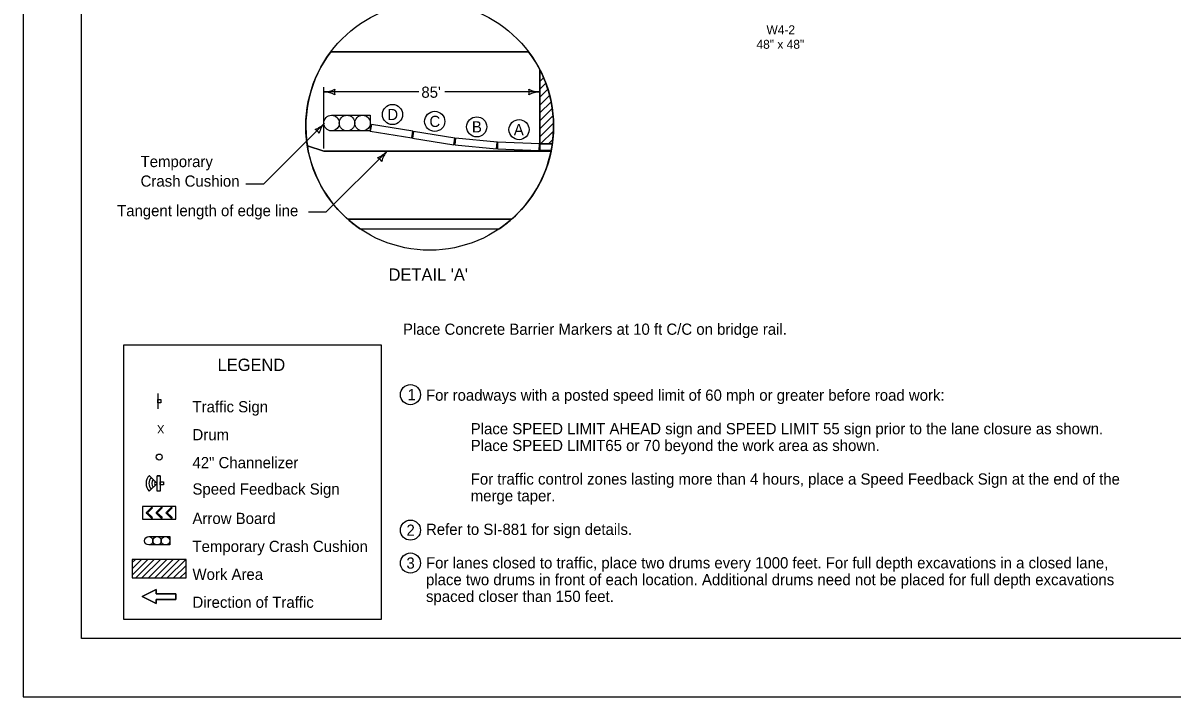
# Model space of a CAD drawing. Extents: x -2135039 to 114557, y -2139150 to -409929.
# Drawn here: x -2135039 to -2132982, y -2139150 to -2137945 of the extents above; entities that cross this region are included whole.
import ezdxf

# ---------------------------------------------------------------- set-up
doc = ezdxf.new("R2010")
doc.units = 0
for name, color, linetype in [('dsnDOTLogo', 7, 'Continuous'), ('dsnStdDimension', 7, 'Continuous'), ('dsnStdLabel', 7, 'Continuous'), ('dsnStdLineWork', 7, 'Continuous'), ('dsnStdNote', 7, 'Continuous'), ('dsnStdShading', 7, 'Continuous'), ('Level 1', 7, 'Continuous'), ('Level 2', 7, 'Continuous'), ('StdDetailLabel', 7, 'Continuous'), ('StdDimension', 7, 'Continuous'), ('StdNote', 7, 'Continuous')]:
    doc.layers.add(name, color=color, linetype=linetype)

msp = doc.modelspace()

# ---------------------------------------------------------------- linework, layer by layer
at = {"layer": 'dsnDOTLogo'}
msp.add_lwpolyline([(-2135038.9, -2139150.4), (-2131694.9, -2139150.4), (-2131694.9, -2136566.4), (-2135038.9, -2136566.4)], close=True, dxfattribs=at)
at = {"layer": 'dsnStdDimension'}
msp.add_line((-2134114.3, -2138156.3), (-2134114.3, -2138059.3), dxfattribs=at)
at = {"layer": 'dsnStdLabel'}
for p, q in [((-2134798, -2138607.5), (-2134798, -2138635)), ((-2134793.3, -2138754.5), (-2134793.3, -2138782)), ((-2134818.1, -2138820.1), (-2134809.3, -2138811.3)), ((-2134800.6, -2138820.1), (-2134791.8, -2138811.3)), ((-2134782.9, -2138820.1), (-2134774.1, -2138811.3)), ((-2134814.1, -2138863.4), (-2134776.6, -2138863.4)), ((-2134776.6, -2138863.4), (-2134776.6, -2138878.4)), ((-2134776.6, -2138878.4), (-2134814.1, -2138878.4)), ((-2134843.7, -2138909.9), (-2134838, -2138904.2)), ((-2134843.7, -2138921.2), (-2134826.7, -2138904.2)), ((-2134843.7, -2138932.5), (-2134815.4, -2138904.2)), ((-2134837.4, -2138937.5), (-2134804.1, -2138904.2)), ((-2134826.1, -2138937.5), (-2134792.8, -2138904.2)), ((-2134814.7, -2138937.5), (-2134781.5, -2138904.2)), ((-2134803.4, -2138937.5), (-2134770.1, -2138904.2)), ((-2134792.1, -2138937.5), (-2134758.8, -2138904.2)), ((-2134780.8, -2138937.5), (-2134747.5, -2138904.2)), ((-2134769.5, -2138937.5), (-2134747, -2138915)), ((-2134758.2, -2138937.5), (-2134747, -2138926.4))]:
    msp.add_line(p, q, dxfattribs=at)
for points in [[(-2134797.9, -2138623.9), (-2134797.9, -2138618.3), (-2134792.3, -2138618.3), (-2134792.3, -2138623.9)], [(-2134798.9, -2138782), (-2134798.9, -2138754.5), (-2134793.3, -2138754.5), (-2134793.3, -2138782)], [(-2134793.3, -2138771), (-2134793.3, -2138765.3), (-2134787.6, -2138765.3), (-2134787.6, -2138771)], [(-2134765.3, -2138809.4), (-2134825.3, -2138809.4), (-2134825.3, -2138832.3), (-2134765.3, -2138832.3)], [(-2134843.7, -2138904.2), (-2134843.7, -2138937.5), (-2134747, -2138937.5), (-2134747, -2138904.2)], [(-2134765.7, -2138965.9), (-2134765.7, -2138975.9), (-2134800.7, -2138975.9), (-2134800.7, -2138983.4), (-2134825.7, -2138970.9), (-2134800.7, -2138958.4), (-2134800.7, -2138965.9)]]:
    msp.add_lwpolyline(points, close=True, dxfattribs=at)
for points in [[(-2134809.3, -2138830.4), (-2134809.3, -2138830.4), (-2134818.1, -2138821.6), (-2134818.1, -2138821.6)], [(-2134807.9, -2138812.8), (-2134807.9, -2138812.8), (-2134816.4, -2138820.9), (-2134807.9, -2138828.9)], [(-2134791.8, -2138830.4), (-2134791.8, -2138830.4), (-2134800.6, -2138821.6), (-2134800.6, -2138821.6)], [(-2134790.3, -2138812.8), (-2134790.4, -2138812.8), (-2134798.8, -2138820.9), (-2134790.3, -2138828.9)], [(-2134774.1, -2138830.4), (-2134774.1, -2138830.4), (-2134782.9, -2138821.6), (-2134783, -2138821.6)], [(-2134772.7, -2138812.8), (-2134772.7, -2138812.8), (-2134781.2, -2138820.9), (-2134772.7, -2138828.9)], [(-2134800.7, -2138965.9), (-2134800.7, -2138958.4), (-2134825.7, -2138970.9), (-2134800.7, -2138983.4), (-2134800.7, -2138975.9), (-2134765.7, -2138975.9), (-2134765.7, -2138965.9), (-2134800.7, -2138965.9)]]:
    msp.add_lwpolyline(points, dxfattribs=at)
for centre, radius in [((-2134311.5, -2138129.5), 221.6), ((-2134487.1, -2138123.6), 13.9), ((-2134459.4, -2138123.6), 13.9), ((-2134431.6, -2138123.6), 13.9), ((-2134795.3, -2138721.1), 5.37), ((-2134795.3, -2138721.1), 5.37), ((-2134814.1, -2138870.9), 7.5), ((-2134814.1, -2138870.9), 7.5), ((-2134799.1, -2138870.9), 7.5), ((-2134799.1, -2138870.9), 7.5), ((-2134784.1, -2138870.9), 7.5), ((-2134784.1, -2138870.9), 7.5)]:
    msp.add_circle(centre, radius, dxfattribs=at)
for centre, start, end in [((-2134817.4, -2138820.9), 134.1616, 224.6098), ((-2134808.6, -2138812), 315.0975, 135.281), ((-2134799.9, -2138820.9), 134.1616, 224.6098), ((-2134791, -2138812), 315.0975, 135.281), ((-2134782.2, -2138820.9), 134.1616, 224.6098), ((-2134773.4, -2138812), 315.0975, 135.281), ((-2134808.6, -2138829.7), 226.201, 47.3602), ((-2134791, -2138829.7), 226.201, 47.3602), ((-2134773.4, -2138829.7), 226.201, 47.3602)]:
    msp.add_arc(centre, 1.03, start, end, dxfattribs=at)
at = {"layer": 'dsnStdLineWork'}
for p, q in [((-2134488.4, -2137996.1), (-2134134.6, -2137996.1)), ((-2134114.3, -2138160.9), (-2134114.3, -2138028.4)), ((-2134114.3, -2138034.9), (-2134112.2, -2138032.7)), ((-2134114.3, -2138049), (-2134107.7, -2138042.4)), ((-2134114.3, -2138063.1), (-2134103.7, -2138052.5)), ((-2134114.3, -2138077.3), (-2134100.1, -2138063.1)), ((-2134114.3, -2138091.4), (-2134097, -2138074.1)), ((-2134114.3, -2138105.6), (-2134094.3, -2138085.6)), ((-2134114.3, -2138119.7), (-2134092.2, -2138097.6)), ((-2134114.3, -2138133.9), (-2134090.8, -2138110.3)), ((-2134114.3, -2138148), (-2134090, -2138123.7)), ((-2134113.1, -2138160.9), (-2134090.1, -2138137.9)), ((-2134530.3, -2138164.4), (-2134501, -2138173.9)), ((-2134098.9, -2138160.9), (-2134091.2, -2138153.1)), ((-2134501, -2138173.9), (-2134094.4, -2138173.9)), ((-2134458.1, -2138295.7), (-2134164.9, -2138295.7))]:
    msp.add_line(p, q, dxfattribs=at)
for points in [[(-2134341.8, -2138138.3), (-2134415.8, -2138126.2), (-2134417.7, -2138138.1), (-2134343.7, -2138150.2)], [(-2134266.3, -2138150.7), (-2134340.3, -2138138.6), (-2134342.2, -2138150.4), (-2134268.2, -2138162.6)], [(-2134190.8, -2138157.9), (-2134265.5, -2138150.8), (-2134266.6, -2138162.8), (-2134192, -2138169.9)], [(-2134115.1, -2138160.9), (-2134190, -2138157.9), (-2134190.5, -2138169.9), (-2134115.5, -2138172.9)]]:
    msp.add_lwpolyline(points, close=True, dxfattribs=at)
for points in [[(-2134094.2, -2138172.9), (-2134114.3, -2138172.9), (-2134114.3, -2138160.9), (-2134092.1, -2138160.9)], [(-2134859.4, -2138521.1), (-2134859.4, -2139011.3), (-2134397.6, -2139011.3), (-2134397.6, -2138521.1), (-2134859.4, -2138521.1)]]:
    msp.add_lwpolyline(points, dxfattribs=at)
at = {"layer": 'dsnStdNote'}
for centre in [(-2134378, -2138108.3), (-2134302.5, -2138120.6), (-2134227.4, -2138130.4), (-2134151.7, -2138135.4), (-2134346, -2138609.5), (-2134346, -2138851.9), (-2134346, -2138910.8)]:
    msp.add_circle(centre, 18, dxfattribs=at)
at = {"layer": 'dsnStdShading'}
for p, q in [((-2134134.6, -2137996.1), (-2134488.4, -2137996.1)), ((-2134530.3, -2138164.4), (-2134501, -2138173.9)), ((-2134501, -2138173.9), (-2134530.3, -2138164.4)), ((-2134114.3, -2138160.9), (-2134092.1, -2138160.9)), ((-2134501, -2138173.9), (-2134094.4, -2138173.9)), ((-2134094.4, -2138173.9), (-2134501, -2138173.9)), ((-2134458.1, -2138295.7), (-2134164.9, -2138295.7)), ((-2134164.9, -2138295.7), (-2134458.1, -2138295.7)), ((-2134435.8, -2138313), (-2134187.2, -2138313))]:
    msp.add_line(p, q, dxfattribs=at)
for points in [[(-2134114.3, -2138028.4), (-2134114.3, -2138068), (-2134114.3, -2138160.9)], [(-2134341.8, -2138138.3), (-2134415.8, -2138126.2), (-2134417.7, -2138138.1), (-2134343.7, -2138150.2), (-2134341.8, -2138138.3)], [(-2134266.3, -2138150.7), (-2134340.3, -2138138.6), (-2134342.2, -2138150.4), (-2134268.2, -2138162.6), (-2134266.3, -2138150.7)], [(-2134190.8, -2138157.9), (-2134265.5, -2138150.8), (-2134266.6, -2138162.8), (-2134192, -2138169.9), (-2134190.8, -2138157.9)], [(-2134115.1, -2138160.9), (-2134190, -2138157.9), (-2134190.5, -2138169.9), (-2134115.5, -2138172.9), (-2134115.1, -2138160.9)], [(-2134092.1, -2138160.9), (-2134114.3, -2138160.9), (-2134114.3, -2138172.9), (-2134094.2, -2138172.9)], [(-2134094.2, -2138172.9), (-2134114.3, -2138172.9), (-2134114.3, -2138160.9), (-2134092.1, -2138160.9)]]:
    msp.add_lwpolyline(points, dxfattribs=at)
for start, end in [(142.9773, 189.0659), (351.8621, 37.0227), (351.8621, 27.1505), (189.0659, 228.5906), (348.7138, 351.8621), (311.4094, 348.45), (348.45, 348.7138), (228.5906, 235.889), (304.111, 311.4094)]:
    msp.add_arc((-2134311.5, -2138129.5), 221.6, start, end, dxfattribs=at)
at = {"layer": 'Level 1'}
msp.add_lwpolyline([(-2134934.4, -2137035.9), (-2131799.4, -2137035.9), (-2131799.4, -2139045.9), (-2134934.4, -2139045.9)], close=True, dxfattribs=at)
at = {"layer": 'Level 2'}
for p, q in [((-2134487.1, -2138109.7), (-2134417.7, -2138109.7)), ((-2134417.7, -2138109.7), (-2134417.7, -2138137.5)), ((-2134417.7, -2138137.5), (-2134487.1, -2138137.5)), ((-2134418.3, -2138138.8), (-2134418.3, -2138138.8)), ((-2134813, -2138754.1), (-2134798.9, -2138768.3)), ((-2134793.3, -2138754.5), (-2134798.9, -2138754.5)), ((-2134798.9, -2138768.3), (-2134813, -2138782.4)), ((-2134793.3, -2138782), (-2134798.9, -2138782))]:
    msp.add_line(p, q, dxfattribs=at)
for centre in [(-2134487.1, -2138123.6), (-2134487.1, -2138123.6), (-2134459.4, -2138123.6), (-2134459.4, -2138123.6), (-2134431.6, -2138123.6), (-2134431.6, -2138123.6)]:
    msp.add_circle(centre, 13.9, dxfattribs=at)
for radius, start, end in [(20.3, 135.88, 224.0313), (15.3, 136.1665, 223.7159), (10.3, 136.7294, 223.0963), (5.32, 138.7005, 221.2995)]:
    msp.add_arc((-2134798.4, -2138768.3), radius, start, end, dxfattribs=at)
at = {"layer": 'StdDimension'}
for p, q in [((-2134501, -2138169.3), (-2134501, -2138059.3)), ((-2134114.3, -2138156.3), (-2134114.3, -2138059.3)), ((-2134331, -2138068), (-2134501, -2138068)), ((-2134114.3, -2138068), (-2134284.3, -2138068)), ((-2134499.4, -2138123.6), (-2134608.2, -2138232.2)), ((-2134387.7, -2138173.9), (-2134496.5, -2138282.5)), ((-2134640.2, -2138232.2), (-2134608.2, -2138232.2)), ((-2134528.5, -2138282.5), (-2134496.5, -2138282.5))]:
    msp.add_line(p, q, dxfattribs=at)
for centre, radius, start, end in [((-2134501, -2138025.5), 42.5, 270, 298.0725), ((-2134501, -2138110.5), 42.5, 61.9275, 90), ((-2134465.4, -2138068), 16.4, 162.2666, 197.7334), ((-2134150, -2138068), 16.4, 342.2666, 17.7333), ((-2134114.3, -2138025.5), 42.5, 241.9275, 270), ((-2134114.3, -2138110.5), 42.5, 90, 118.0725), ((-2134531.4, -2138095.4), 42.5, 290.4723, 318.5448), ((-2134523.1, -2138150.3), 16.4, 30.8115, 66.2782), ((-2134467.7, -2138151.7), 42.5, 138.5448, 166.6173), ((-2134419.7, -2138145.7), 42.5, 290.4723, 318.5448), ((-2134356, -2138202), 42.5, 138.5448, 166.6173), ((-2134411.4, -2138200.6), 16.4, 30.8115, 66.2782)]:
    msp.add_arc(centre, radius, start, end, dxfattribs=at)

# ---------------------------------------------------------------- texts
at = {"layer": 'dsnStdLabel'}
for s, height, p in [('W4-2', 16, (-2133709.1, -2137964.7)), ('48" x 48"', 16, (-2133727, -2137990.7)), ('LEGEND', 22, (-2134690.9, -2138567.1)), ('Traffic Sign', 20, (-2134735.8, -2138641.1)), ('Drum', 20, (-2134735.8, -2138691.1)), ('42" Channelizer ', 20, (-2134735.8, -2138741.1)), ('Speed Feedback Sign', 20, (-2134735.8, -2138788.3)), ('Arrow Board', 20, (-2134735.8, -2138840.9)), ('Temporary Crash Cushion', 20, (-2134735.8, -2138890.9)), ('Work Area', 20, (-2134735.8, -2138940.9)), ('Direction of Traffic', 20, (-2134735.8, -2138990.9))]:
    msp.add_text(s, height=height, dxfattribs=at).set_placement(p)
msp.add_text('X', height=15, rotation=180, dxfattribs=at).set_placement((-2134785.9, -2138663.6))
at = {"layer": 'dsnStdNote'}
for s, p in [('D', (-2134387.3, -2138118.3)), ('C', (-2134312, -2138130.6)), ('B', (-2134236, -2138140.4)), ('A', (-2134161.1, -2138145.4)), ('1', (-2134351.2, -2138619.5)), ('2', (-2134353, -2138861.9)), ('3', (-2134353.1, -2138920.8))]:
    msp.add_text(s, height=20, dxfattribs=at).set_placement(p)
at = {"layer": 'StdDetailLabel'}
msp.add_text("DETAIL 'A'", height=22, dxfattribs=at).set_placement((-2134385, -2138405.7))
at = {"layer": 'StdDimension'}
for s, p in [("85'", (-2134326.4, -2138078.4)), ('Temporary ', (-2134828.6, -2138202.4)), ('Crash Cushion', (-2134828.6, -2138237.4)), ('Tangent length of edge line', (-2134870.7, -2138290.2))]:
    msp.add_text(s, height=20, dxfattribs=at).set_placement(p)
at = {"layer": 'StdNote'}
for s, p in [('Place Concrete Barrier Markers at 10 ft C/C on bridge rail.', (-2134359.3, -2138502.4)), ('For roadways with a posted speed limit of 60 mph or greater before road work:', (-2134318.1, -2138620.4)), ('Place SPEED LIMIT AHEAD sign and SPEED LIMIT 55 sign prior to the lane closure as shown. ', (-2134238.1, -2138680.4)), ('Place SPEED LIMIT65 or 70 beyond the work area as shown.', (-2134238.1, -2138710.4)), ('For traffic control zones lasting more than 4 hours, place a Speed Feedback Sign at the end of the ', (-2134238.1, -2138770.4)), ('merge taper.', (-2134238.1, -2138800.4)), ('Refer to SI-881 for sign details.', (-2134318.1, -2138860.4)), ('For lanes closed to traffic, place two drums every 1000 feet. For full depth excavations in a closed lane, ', (-2134318.1, -2138920.4)), ('place two drums in front of each location. Additional drums need not be placed for full depth excavations ', (-2134318.1, -2138950.4)), ('spaced closer than 150 feet.', (-2134318.1, -2138980.4))]:
    msp.add_text(s, height=20, dxfattribs=at).set_placement(p)

doc.saveas('drawing.dxf')
